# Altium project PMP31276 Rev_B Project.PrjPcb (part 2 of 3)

## Sheet PMP31276 Rev_B LLC Schematic.SchDoc: LLC Resonant converter
size 431 x 317 mm; Date: Not shown in title block; ApprovedBy: Not shown in title block; CheckedBy: Not shown in title block; Author: Not shown in title block; CompanyName: Not shown in title block; DrawnBy: R. Scibilia; Engineer: R. Scibilia; Organization: Not shown in title block; Address1: Not shown in title block; Address2: Not shown in title block; Address3: Not shown in title block; Address4: Not shown in title block; DocumentNumber: 1; Revision: Use project parameter SCH_Rev; SheetNumber: 2; SheetTotal: 5; PageSetup: Record=PageOptions¦CenterHorizontal=True¦CenterVertical=True¦PrintScale=1.00¦XCorrection=1.00¦YCorrection=1.00¦PrintKind=0¦BorderSize=5000000¦LeftOffset=0¦BottomOffset=0¦Orientation=2¦PaperLength=1000¦PaperWidth=1000¦Scale=100¦PaperSource=15¦PrintQuality=600¦MediaType=1¦DitherType=10¦PaperKind=Letter¦PrintScaleMode=1
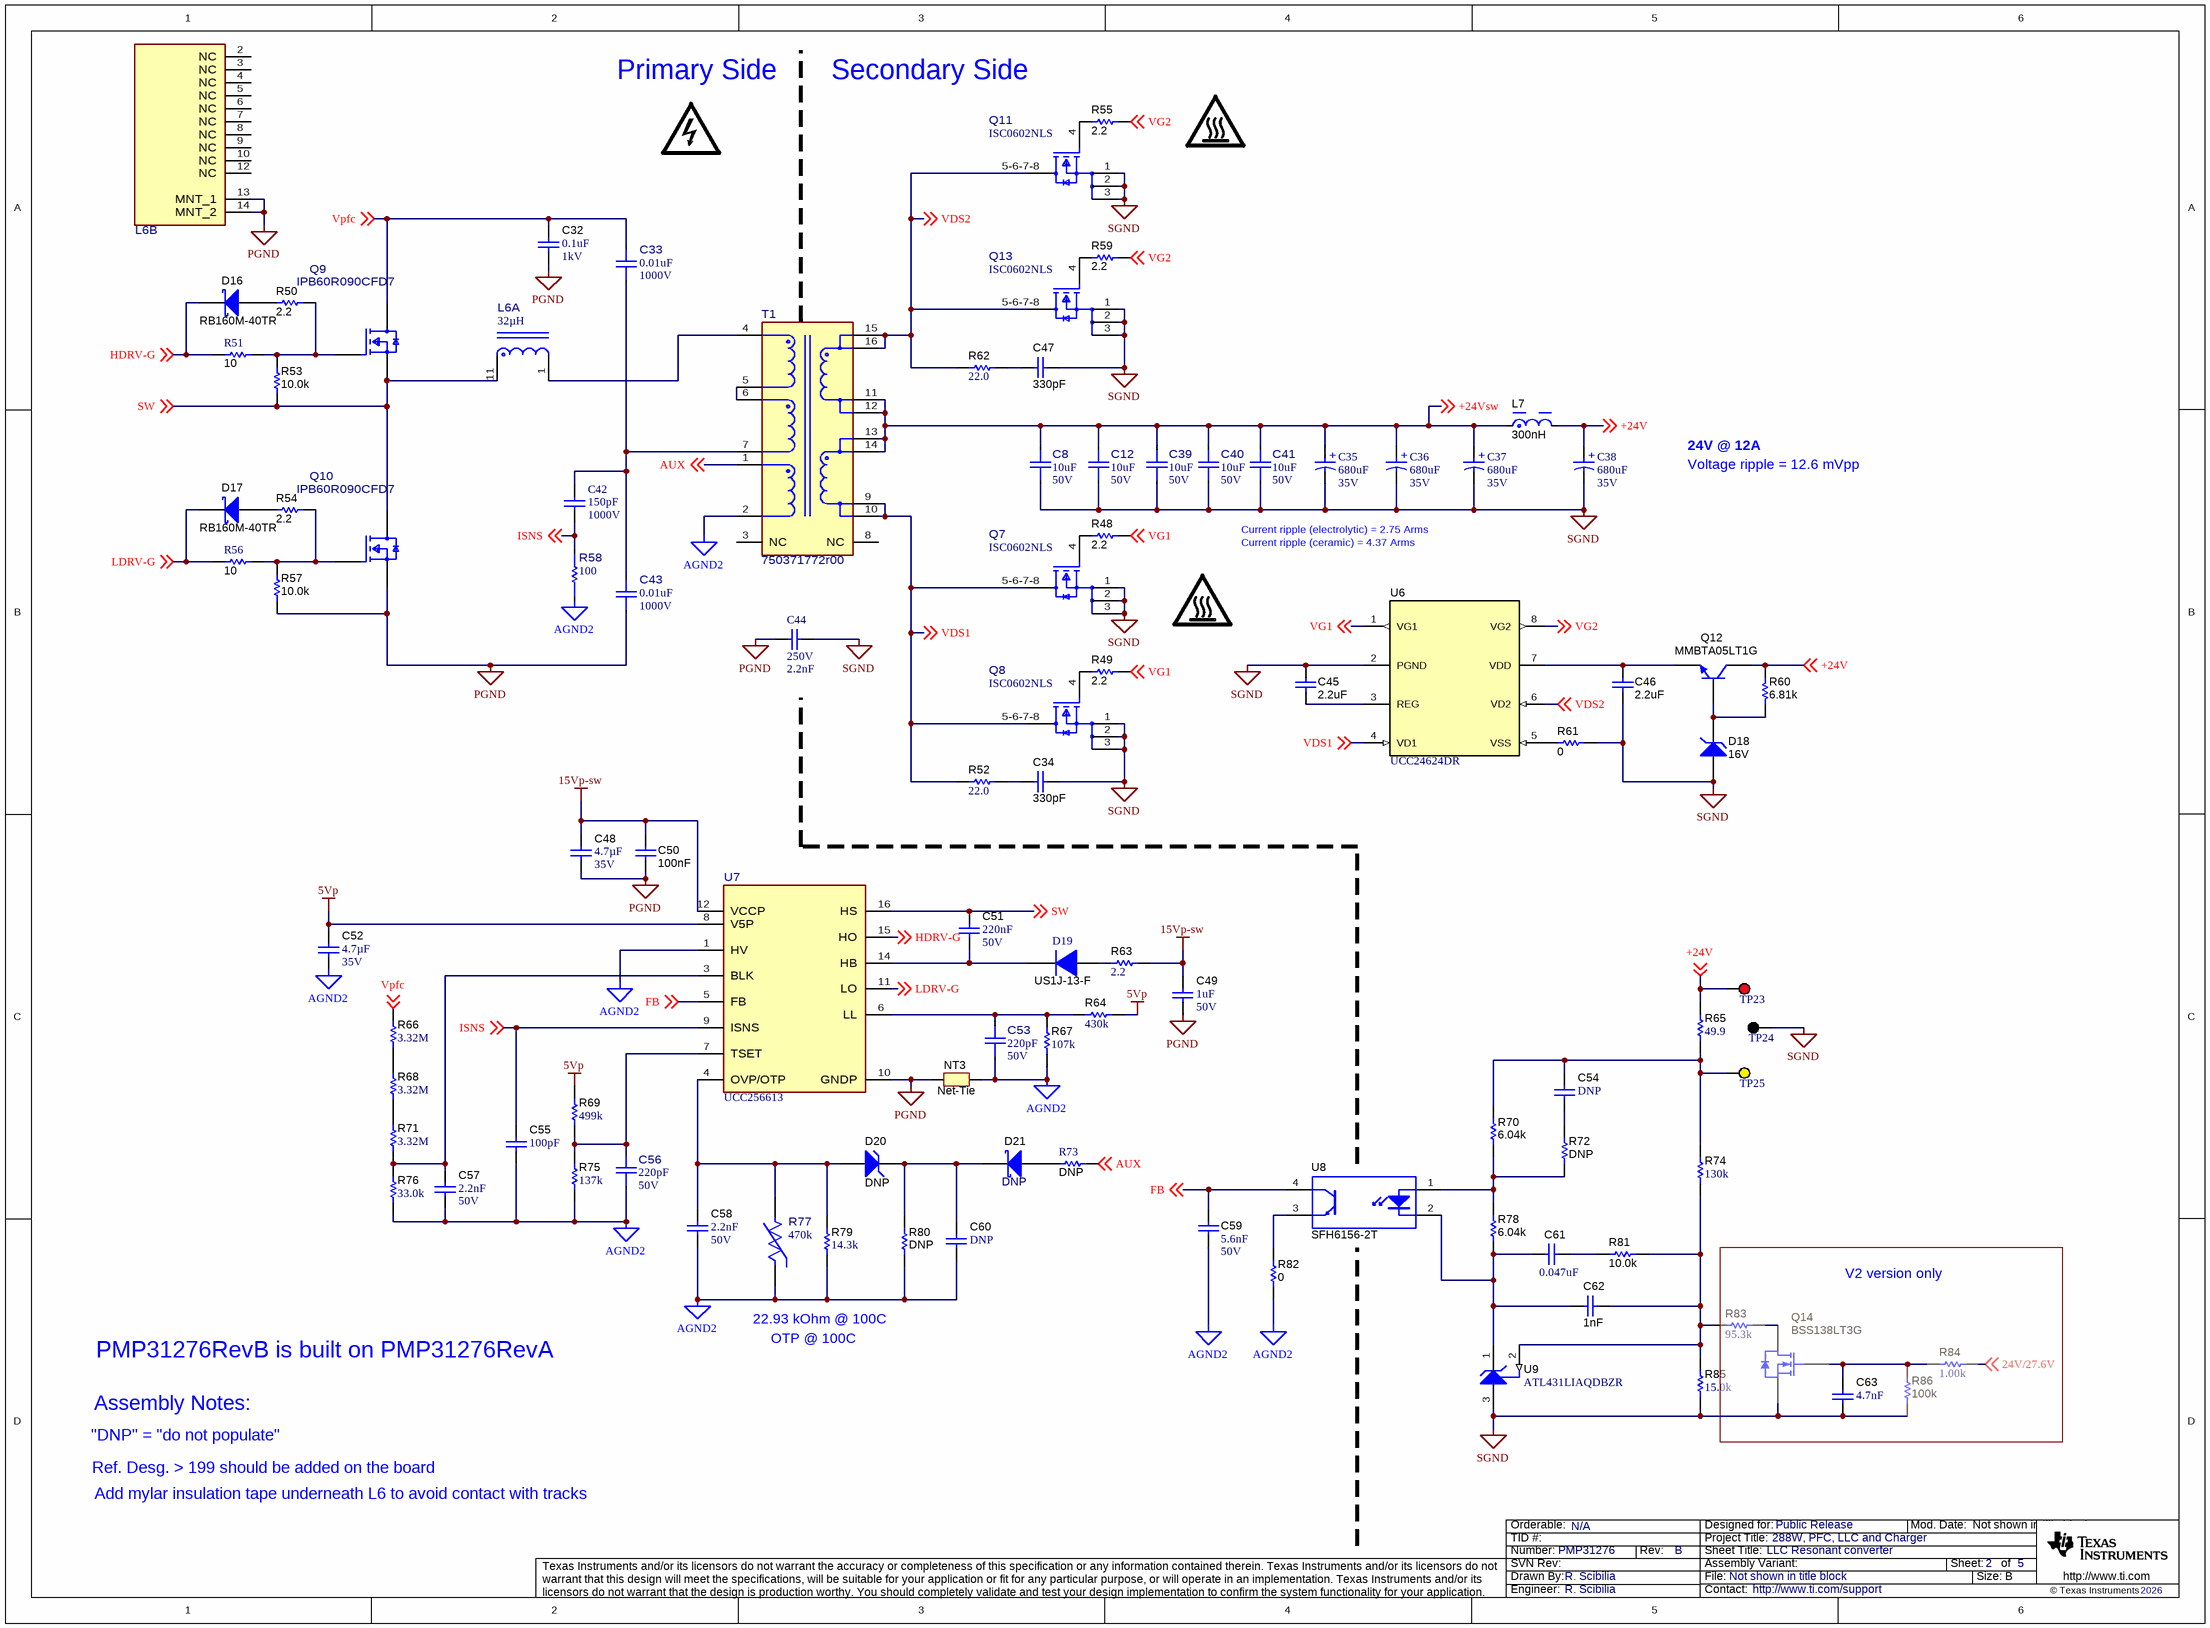
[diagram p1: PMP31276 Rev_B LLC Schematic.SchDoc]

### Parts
(Parts that share a designator on the sheet are numbered #1, #2 ... from top to bottom, then left to right.)
C8  ValueDisplayed: 10uF  VDC_V: 50V  [FP-885012209073_1210-MFG]  (hidden comment: 885012209073)
C12  ValueDisplayed: 10uF  VDC_V: 50V  [FP-885012209073_1210-MFG]  (hidden comment: 885012209073)
C32  VDC_V: 1kV  ValueDisplayed: 0.1uF  [1812_254]  (hidden comment: 885382211002)
C33  VDC_V: 1000V  ValueDisplayed: 0.01uF  [FP-CKC18C103KWGACAUTO_1812-MFG]  (hidden comment: CKC18C103JDGACAUTO)
C34  ValueDisplayed: 330pF  [1206]  (hidden comment: 885012008070)
C35  value 680uF  Rated Voltage (DC): 35V  [WCAP-ASLL_D12.5H14]  (hidden comment: 865060562010)
C36  value 680uF  Rated Voltage (DC): 35V  [WCAP-ASLL_D12.5H14]  (hidden comment: 865060562010)
C37  value 680uF  Rated Voltage (DC): 35V  [WCAP-ASLL_D12.5H14]  (hidden comment: 865060562010)
C38  value 680uF  Rated Voltage (DC): 35V  [WCAP-ASLL_D12.5H14]  (hidden comment: 865060562010)
C39  ValueDisplayed: 10uF  VDC_V: 50V  [FP-885012209073_1210-MFG]  (hidden comment: 885012209073)
C40  ValueDisplayed: 10uF  VDC_V: 50V  [FP-885012209073_1210-MFG]  (hidden comment: 885012209073)
C41  ValueDisplayed: 10uF  VDC_V: 50V  [FP-885012209073_1210-MFG]  (hidden comment: 885012209073)
C42  value 150pF  Rated Voltage (DC): 1000V  [WCAP-CSMH_1206_L3.2W1.6H1.25]  (hidden comment: 885342208016)
C43  VDC_V: 1000V  ValueDisplayed: 0.01uF  [FP-CKC18C103KWGACAUTO_1812-MFG]  (hidden comment: CKC18C103JDGACAUTO)
C44  value 2.2nF  Rated Voltage (AC): 250V  [WCAP-CSSA_2211_L5.7W2.8H2.5]  (hidden comment: 8853522130151)
C45  ValueDisplayed: 2.2uF  [0603]  (hidden comment: GRM188R6YA225KA12D)
C46  ValueDisplayed: 2.2uF  [0603]  (hidden comment: GRM188R6YA225KA12D)
C47  ValueDisplayed: 330pF  [1206]  (hidden comment: 885012008070)
C48  Cap_F: 4.7µF  VDC_V: 35V  [0805_HV]  (hidden comment: C2012X7R1V475K125AC)
C49  VDC_V: 50V  ValueDisplayed: 1uF  [0603]  (hidden comment: C1608X6S1H105K080AC)
C50  Cap_F: 100nF  [0603]  (hidden comment: 885012206095)
C51  Cap_F: 220nF  VDC_V: 50V  [0603]  (hidden comment: C1608X7R1H224K080AB)
C52  Cap_F: 4.7µF  VDC_V: 35V  [0805_HV]  (hidden comment: C2012X7R1V475K125AC)
C53  ValueDisplayed: 220pF  VDC_V: 50V  [FP-C0603C221J5GAC7867_0603-IPC_B]  (hidden comment: C0603C221J5GAC7867)
C54  DNP  [0603]
C55  ValueDisplayed: 100pF  [0603]  (hidden comment: 885012006057)
C56  ValueDisplayed: 220pF  VDC_V: 50V  [FP-C0603C221J5GAC7867_0603-IPC_B]  (hidden comment: C0603C221J5GAC7867)
C57  Cap_F: 2.2nF  VDC_V: 50V  [0603]  (hidden comment: C0603C222K5RAC)
C58  Cap_F: 2.2nF  VDC_V: 50V  [0603]  (hidden comment: C0603C222K5RAC)
C59  Cap_F: 5.6nF  VDC_V: 50V  [0603]  (hidden comment: C0603C222K5RACTU)
C60  DNP  [0603]
C61  ValueDisplayed: 0.047uF  [0603]  (hidden comment: C1608X5R1H473K080AA)
C62  Cap_F: 1nF  [0603]  (hidden comment: 885012206083)
C63  Cap_F: 4.7nF  [0603]  (hidden comment: 885012206087)
D16  RB160M-40TR  [SOD-123]
D17  RB160M-40TR  [SOD-123]
D18  value 16V  [SOD-323]  (hidden comment: MM3Z16VST1G)
D19  value US1J-13-F  [SMA]  (hidden comment: DIODE)
D20  DNP  [SOD-323]
D21  DNP  [SOD-123F]
L6  Ind_H: 32µH  [FP-750371775r00_PTH_22MM0_22MM0-MFG]  (hidden comment: 750371775r00)  (parts A,B of 2)
L7  value 300nH  [FP-7443081030_SMT_IND_9MM4_6MM2-MFG]  (hidden comment: 7443081030)
LOGO?#4  CAUTION HOT SURFACE  [IEC_HotSurface_Small]  (value not drawn)  (graphical)
LOGO?#5  DANGER HIGH VOLTAGE  [IEC_HighVoltage_Small]  (value not drawn)  (graphical)
LOGO?#6  CAUTION HOT SURFACE  [IEC_HotSurface_Small]  (value not drawn)  (graphical)
NT3  Net-Tie  [Net-Tie_20milWide_60milLong]  (net tie, no BOM)
Q7  ISC0602NLS  [FP-ISC0603NLSATMA1_TDSON-8-MFG]
Q8  ISC0602NLS  [FP-ISC0603NLSATMA1_TDSON-8-MFG]
Q9  IPB60R090CFD7  [FP-IPB60R105CFD7ATMA1_D2PAK-MFG]
Q10  IPB60R090CFD7  [FP-IPB60R105CFD7ATMA1_D2PAK-MFG]
Q11  ISC0602NLS  [FP-ISC0603NLSATMA1_TDSON-8-MFG]
Q12  MMBTA05LT1G  [SOT-23]
Q13  ISC0602NLS  [FP-ISC0603NLSATMA1_TDSON-8-MFG]
Q14  BSS138LT3G  [SOT-23]
R48  ValueDisplayed: 2.2  [0805_HV]  (hidden comment: RC0805JR-072R2L)
R49  ValueDisplayed: 2.2  [0805_HV]  (hidden comment: RC0805JR-072R2L)
R50  ValueDisplayed: 2.2  [0805_HV]  (hidden comment: RC0805JR-072R2L)
R51  ValueDisplayed: 10  [0805_HV1]  (hidden comment: Resistor)
R52  ValueDisplayed: 22.0  [1206]  (hidden comment: RC1206FR-0722RL)
R53  ValueDisplayed: 10.0k  [0603]  (hidden comment: Resistor)
R54  ValueDisplayed: 2.2  [0805_HV]  (hidden comment: RC0805JR-072R2L)
R55  ValueDisplayed: 2.2  [0805_HV]  (hidden comment: RC0805JR-072R2L)
R56  ValueDisplayed: 10  [0805_HV1]  (hidden comment: Resistor)
R57  ValueDisplayed: 10.0k  [0603]  (hidden comment: Resistor)
R58  value 100  [FP-WCR0805LF1000FPLT_0805-MFG]  (hidden comment: WCR0805LF1000FPLT)
R59  ValueDisplayed: 2.2  [0805_HV]  (hidden comment: RC0805JR-072R2L)
R60  ValueDisplayed: 6.81k  [0603]  (hidden comment: RC0603FR-076K81L)
R61  ValueDisplayed: 0  [0603]  (hidden comment: RMCF0603ZT0R00)
R62  ValueDisplayed: 22.0  [1206]  (hidden comment: RC1206FR-0722RL)
R63  ValueDisplayed: 2.2  [0805_HV]  (hidden comment: RC0805JR-072R2L)
R64  ValueDisplayed: 430k  [0603]  (hidden comment: RC0603FR-07430KL)
R65  ValueDisplayed: 49.9  [0603]  (hidden comment: RC0603FR-0749R9L)
R66  ValueDisplayed: 3.32M  [1206]  (hidden comment: CRCW12063M32FKEA)
R67  ValueDisplayed: 107k  [0603]  (hidden comment: RC0603FR-07107KL)
R68  ValueDisplayed: 3.32M  [1206]  (hidden comment: CRCW12063M32FKEA)
R69  ValueDisplayed: 499k  [0603]  (hidden comment: RC0603FR-07499KL)
R70  ValueDisplayed: 6.04k  [0603]  (hidden comment: Resistor)
R71  ValueDisplayed: 3.32M  [1206]  (hidden comment: CRCW12063M32FKEA)
R72  DNP  [0603]
R73  DNP  [0805_HV1]
R74  ValueDisplayed: 130k  [0603]  (hidden comment: RC0603FR-07130KL)
R75  ValueDisplayed: 137k  [0603]  (hidden comment: RC0603FR-07137KL)
R76  ValueDisplayed: 33.0k  [0603]  (hidden comment: RC0603FR-0733KL)
R77  value 470k  [FP-B57371V2474J060_0603-MFG]  (hidden comment: B57371V2474J060)
R78  ValueDisplayed: 6.04k  [0603]  (hidden comment: Resistor)
R79  ValueDisplayed: 14.3k  [0603]  (hidden comment: RC0603FR-0714K3L)
R80  DNP  [0603]
R81  ValueDisplayed: 10.0k  [0603]  (hidden comment: Resistor)
R82  ValueDisplayed: 0  [0603]  (hidden comment: RMCF0603ZT0R00)
R83  ValueDisplayed: 95.3k  [0603]  (hidden comment: RC0603FR-0795K3L)
R84  ValueDisplayed: 1.00k  [0603]  (hidden comment: RC0603FR-071KL)
R85  ValueDisplayed: 15.0k  [0603]  (hidden comment: RC0603FR-0715KL)
R86  ValueDisplayed: 100k  [0603]  (hidden comment: CRCW0603100KFKEA)
T1  750371772r00  [FP-750371772r00_PTH16_41MM9_44MM0-MFG]
TP23  5000  [Keystone5000]  (value not drawn)
TP24  5001  [Keystone5001]  (value not drawn)
TP25  5004  [Keystone5004]  (value not drawn)
U6  UCC24624DR  [D0008A_N]
U7  UCC256613  [DDB0014A-MFG]
U8  SFH6156-2T  [SMD-4]
U9  ATL431LIAQDBZR  [DBZ0003A_N]

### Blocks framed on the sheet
V2 version only: C63 Q14 R83 R84 R86

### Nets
5Vp: C52.1 R64.2 R69.2 U7.8(V5P)
15Vp-sw: C48.1 C49.1 C50.1 R63.2 U7.12(VCCP)
AGND2: C52.2 C53.1 C55.2 C56.1 C57.2 C58.2 C59.2 C60.2 NT3.2 R58.1 R67.1 R75.1 R76.1 R77.1 R79.1 R80.2 R82.1 T1.2 U7.1(HV)
PGND: C32.2 C43.1 C44.1 C48.2 C49.2 C50.2 L6.13(MNT_1) L6.14(MNT_2) NT3.1 Q10.3(Source) R57.1 U7.10(GNDP)
SGND: C8.1 C12.1 C34.1 C35.2(N) C36.2(N) C37.2(N) C38.2(N) C39.1 C40.1 C41.1 C44.2 C45.1 C46.2 C47.1 C63.2 D18.2(A) Q7.1(Source) Q7.2(Source) Q7.3(Source) Q8.1(Source) Q8.2(Source) Q8.3(Source) Q11.1(Source) Q11.2(Source) Q11.3(Source) Q13.1(Source) Q13.2(Source) Q13.3(Source) Q14.2(S) R61.1 R85.1 R86.2 TP24.1 U6.2(PGND) U9.3(ANODE)
24V/27.6V: R84.1 ; off-sheet 24V/27.6V
+24V: C38.1(P) L7.2 Q12.3(C) R60.2 R65.2 TP23.1 ; off-sheet +24V
+24Vsw: C8.2 C12.2 C35.1(P) C36.1(P) C37.1(P) C39.2 C40.2 C41.2 L7.1 T1.11 T1.12 T1.13 T1.14 ; off-sheet +24Vsw
AUX: R73.2 T1.1 ; off-sheet AUX
FB: C59.1 U7.5(FB) U8.4(C) ; off-sheet FB
HDRV-G: D16.1(K) R51.1 U7.15(HO) ; off-sheet HDRV-G
ISNS: C42.1 C55.1 R58.2 U7.9(ISNS) ; off-sheet ISNS
LDRV-G: D17.1(K) R56.1 U7.11(LO) ; off-sheet LDRV-G
SW: C51.1 L6.11 Q9.3(Source) Q10.4(Drain) R53.1 U7.16(HS) ; off-sheet SW
VDS1: Q7.5-6-7-8(Drain) Q8.5-6-7-8(Drain) R52.1 T1.9 T1.10 U6.4(VD1) ; off-sheet VDS1
VDS2: Q11.5-6-7-8(Drain) Q13.5-6-7-8(Drain) R62.1 T1.15 T1.16 U6.6(VD2) ; off-sheet VDS2
VG1: R48.1 R49.1 U6.1(VG1) ; off-sheet VG1
VG2: R55.1 R59.1 U6.8(VG2) ; off-sheet VG2
Vpfc: C32.1 C33.2 Q9.4(Drain) R66.2 ; off-sheet Vpfc
NetC33_1: C33.1 C42.2 C43.2 T1.7
NetC34_2: C34.2 R52.2
NetC45_2: C45.2 U6.3(REG)
NetC46_1: C46.1 Q12.2(E) U6.7(VDD)
NetC47_2: C47.2 R62.2
NetC51_2: C51.2 D19.1(K) U7.14(HB)
NetC53_2: C53.2 R64.1 R67.2 U7.6(LL)
NetC54_1: C54.1 R65.1 R70.2 R74.2 TP25.1
NetC54_2: C54.2 R72.1
NetC56_2: C56.2 R69.1 R75.2 U7.7(TSET)
NetC57_1: C57.1 R71.1 R76.2 U7.3(BLK)
NetC58_1: C58.1 D20.2(A) R77.2 R79.2 U7.4(OVP/OTP)
NetC60_1: C60.1 D20.1(K) D21.1(K) R80.1
NetC61_1: C61.1 R81.1
NetC61_2: C61.2 C62.1 R78.1 U8.2(K) U9.1(CATHODE)
NetC62_2: C62.2 R74.1 R81.2 R83.1 R85.2 U9.2(REF)
NetC63_1: C63.1 Q14.1(G) R84.2 R86.1
NetD16_2: D16.2(A) R50.1
NetD17_2: D17.2(A) R54.1
NetD18_1: D18.1(K) Q12.1(B) R60.1
NetD19_2: D19.2(A) R63.1
NetD21_2: D21.2(A) R73.1
NetL6_1: L6.1 T1.4
NetQ7_4: Q7.4(Gate) R48.2
NetQ8_4: Q8.4(Gate) R49.2
NetQ9_1: Q9.1(Gate) R50.2 R51.2 R53.2
NetQ10_1: Q10.1(Gate) R54.2 R56.2 R57.2
NetQ11_4: Q11.4(Gate) R55.2
NetQ13_4: Q13.4(Gate) R59.2
NetQ14_3: Q14.3(D) R83.2
NetR61_2: R61.2 U6.5(VSS)
NetR66_1: R66.1 R68.2
NetR68_1: R68.1 R71.2
NetR70_1: R70.1 R72.2 R78.2 U8.1(A)
NetR82_2: R82.2 U8.3(E)
NetT1_5: T1.5 T1.6

Not connected (* = marked no-connect by the designer): L6 2(NC) 3(NC) 4(NC) 5(NC) 6(NC) 7(NC) 8(NC) 9(NC) 10(NC) 12(NC); T1 3(NC) 8(NC)

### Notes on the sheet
- (near LOGO?#5) Primary Side
- Secondary Side
- 24V @ 12A
- Voltage ripple = 12.6 mVpp
- Current ripple (electrolytic) = 2.75 Arms
- Current ripple (ceramic) = 4.37 Arms
- 22.93 kOhm @ 100C
- PMP31276RevB is built on PMP31276RevA
- OTP @ 100C
- Assembly Notes:
- "DNP" = "do not populate"
- Ref. Desg. > 199 should be added on the board
- Add mylar insulation tape underneath L6 to avoid contact with tracks

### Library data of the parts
C8 C12 C39-C41 = CMP-0097489-1: 10 µF ±10% 50V Ceramic Capacitor X7R 1210 (3225 Metric); Manufacturer: Wurth Electronics; SizeZ_mm: 2.8mm; AEC Qualified: No; Value: 10µF; TempCo: 15%
C32 = CMP-0009326-2: CAP, CERM, 0.1 uF, 1000 V, +/- 10%, X7R, 1812; Manufacturer: Wuerth; TaMin_C: -55°C; Polarized: N; SizeAreaWB_mm2: 23.1; Value1: Unknown; U/M: EA; Value: 0.1uF; TaMax_C: 125°C; SizeZ_mm: 2.54; SizeX_mm: 4.5; SizeY_mm: 3.2; Cap_Case: 1812; Value2: 1000V; SizeArea_mm2: 14.4; Cap_F: 100nF; AEC Category: Q200
C33 C43 = CMP-0097104-1: 10000 pF ±5% 1000V Ceramic Capacitor C0G, NP0 1812 (4532 Metric); Manufacturer: KEMET; TempCo: 30ppm/°C; Value: 10nF; AEC Grade: Grade 0; SizeZ_mm: 2.2mm; AEC Qualified: Yes; Tolerance_%: 10%
C34 C47 = CMP-0008475-2: CAP, CERM, 330 pF, 100 V, +/- 5%, C0G/NP0, 1206; Manufacturer: Wuerth; TaMin_C: -55°C; ESR_ohm: 3.92d; Polarized: N; SizeAreaWB_mm2: 10.92; Value1: 0.392 ohm; U/M: EA; Value: 330pF; TaMax_C: 125°C; SizeZ_mm: 1.35; SizeX_mm: 3.2; SizeY_mm: 1.6; Value2: 100V; SizeArea_mm2: 5.12; CompType: Capacitor; AEC Category: Q200
C35-C38 = CMP-0110502-1: WCAP-ASLL Aluminum Electrolytic Capacitor, V-Chip, D12.5 x H14mm, 680µF, 35V; Manufacturer: Wurth Elektronik; Capacitance Tolerance: +/-20%; Dissipation Factor: 14%; Endurance: 5000h; Leakage Current: 238uA; Ripple Current: 1150mA; Technical Reference: ASEH140681M035DVCTGE000
C42 = CMP-0108719-1: WCAP-CSMH Multilayer Ceramic Chip Capacitor, Mid and High Voltage, size 1206, X7R Class II, 150pF, 1000VDC; Manufacturer: Wurth Elektronik; Capacitance Tolerance: 10%; Case/Size Code: 1206; Dissipation Factor: 2.5%; Insulation Resistance: 10GOhm; Technical Reference: X7R1206151KA00DFCT10000
C44 = CMP-0112567-1: WCAP-CSSA Multilayer Ceramic Chip Safety Capacitor, size 2211, X7R Class II, 2.2nF, 250VAC; Manufacturer: Wurth Elektronik; Capacitance Tolerance: +/-10%; Case/Size Code: 2211; Dissipation Factor: 2.5%; Impulse Voltage: 5000VDC; Insulation Resistance: 10GOhm; Safety Class: X1/Y2; Technical Reference: X7R2211222KE00IFCT1B000
C45 C46 = CMP-0007356-5: CAP, CERM, 2.2 uF, 35 V, +/- 10%, X5R, 0603; Manufacturer: MuRata; TaMin_C: -55°C; Polarized: N; SizeAreaWB_mm2: 4.68; Value1: Unknown; U/M: EA; Value: 2.2uF; TaMax_C: 85°C; SizeZ_mm: 1; SizeX_mm: 1.6; SizeY_mm: 0.8; Value2: 35V; SizeArea_mm2: 1.28; CompType: Capacitor; Cap_F: 2.2µF; AEC Category: Q200
C48 C52 = CMP-0007885-2: CAP, CERM, 4.7 uF, 35 V, +/- 10%, X7R, 0805; Manufacturer: TDK; TaMin_C: -55°C; ESR_ohm: 2.346m; Polarized: N; SizeAreaWB_mm2: 6.75; Value1: 0.002346 ohm; U/M: EA; Value: 4.7uF; TaMax_C: 125°C; SizeZ_mm: 1.45; SizeX_mm: 2; SizeY_mm: 1.25; Cap_Case: 0805; SizeArea_mm2: 2.5; IRMS_A: 4.2602A; AEC Category: Q200
C49 = CMP-0007029-4: CAP, CERM, 1 uF, 50 V, +/- 10%, X6S, 0603; Manufacturer: TDK; TaMin_C: -55°C; ESR_ohm: 5.522m; Polarized: N; SizeAreaWB_mm2: 4.68; Value1: 0.005522 ohm; U/M: EA; Value: 1uF; TaMax_C: 105°C; SizeZ_mm: 1; SizeX_mm: 1.6; SizeY_mm: 0.8; SizeArea_mm2: 1.28; Cap_F: 1µF; IRMS_A: 2.2162A; AEC Category: Q200
C50 = CMP-0006837-3: CAP, CERM, 0.1 uF, 50 V, +/- 10%, X7R, 0603; Manufacturer: Wurth Elektronik; TaMin_C: -55°C; Polarized: N; SizeAreaWB_mm2: 4.68; Value1: Unknown; U/M: EA; Value: 0.1uF; TaMax_C: 125°C; SizeZ_mm: 1; SizeX_mm: 1.6; SizeY_mm: 0.8; Value2: 50V; SizeArea_mm2: 1.28; AEC Category: Q200
C51 = CMP-0007047-4: CAP, CERM, 0.22 uF, 50 V, +/- 10%, X7R, 0603; Manufacturer: TDK; TaMin_C: -55°C; ESR_ohm: 21.699m; Polarized: N; SizeAreaWB_mm2: 4.68; Value1: 0.021699 ohm; U/M: EA; Value: 0.22uF; TaMax_C: 125°C; SizeZ_mm: 1; SizeX_mm: 1.6; SizeY_mm: 0.8; SizeArea_mm2: 1.28; IRMS_A: 1.125A; AEC Category: Q200
C53 C56 = CMP-0045670-1: 220 pF ±5% 50V Ceramic Capacitor C0G, NP0 0603 (1608 Metric); Manufacturer: KEMET; AEC Qualified: No; SizeZ_mm: 0.87mm; TempCo: 30ppm/°C; Value: 220pF
C54 C60 = CMP-0007029-4: TaMin_C: -55°C; Polarized: N; TempCo: X6S; SizeAreaWB_mm2: 4.68; U/M: EA; TaMax_C: 105°C; Tolerance_%: 10%; SizeZ_mm: 1; SizeX_mm: 1.6; SizeY_mm: 0.8; SizeArea_mm2: 1.28; AEC Category: Q200
C55 = CMP-0006822-4: CAP, CERM, 100 pF, 50 V, +/- 5%, C0G/NP0, 0603; Manufacturer: Wurth Elektronik; TaMin_C: -55°C; Polarized: N; SizeAreaWB_mm2: 4.68; Value1: Unknown; U/M: EA; Value: 100pF; TaMax_C: 125°C; SizeZ_mm: 1; SizeX_mm: 1.6; SizeY_mm: 0.8; Value2: 50V; SizeArea_mm2: 1.28; AEC Category: Q200
C57 C58 = CMP-0006897-4: CAP, CERM, 2200 pF, 50 V, +/- 10%, X7R, 0603; Manufacturer: Kemet; TaMin_C: -55°C; Polarized: N; SizeAreaWB_mm2: 4.68; Value1: Unknown; U/M: EA; Value: 2200pF; TaMax_C: 125°C; SizeZ_mm: 1; SizeX_mm: 1.6; SizeY_mm: 0.8; SizeArea_mm2: 1.28; AEC Category: Q200
C59 = CMP-0006898-4: CAP, CERM, 5600 pF, 50 V, +/- 10%, X7R, 0603; Manufacturer: Kemet; PartNumber: C0603C562K5RACTU; TaMin_C: -55°C; Polarized: N; SizeAreaWB_mm2: 4.68; Value1: Unknown; U/M: EA; Value: 5600pF; TaMax_C: 125°C; SizeZ_mm: 1; SizeX_mm: 1.6; SizeY_mm: 0.8; SizeArea_mm2: 1.28; AEC Category: Q200
C61 = CMP-0007015-5: CAP, CERM, 0.047 uF, 50 V, +/- 10%, X5R, 0603; Manufacturer: TDK; TaMin_C: -55°C; ESR_ohm: 49.007m; Polarized: N; SizeAreaWB_mm2: 4.68; Value1: 0.049007 ohm; U/M: EA; TaMax_C: 85°C; SizeZ_mm: 1; SizeX_mm: 1.6; SizeY_mm: 0.8; Value2: 50V; SizeArea_mm2: 1.28; Cap_F: 47nF; IRMS_A: 767.528mA; AEC Category: Q200
C62 = CMP-0064933-4: CAP, CERM, 1000 pF, 50 V,+/- 10%, X7R, 0603; Manufacturer: Wurth Elektronik; TaMin_C: -55°C; Polarized: N; SizeAreaWB_mm2: 4.68; Value1: Unknown; U/M: EA; Value: 1000pF; TaMax_C: 125°C; SizeZ_mm: 1; SizeX_mm: 1.6; SizeY_mm: 0.8; Value2: 50V; SizeArea_mm2: 1.28; AEC Category: Q200
C63 = CMP-0006835-4: CAP, CERM, 4700 pF, 50 V, +/- 10%, X7R, 0603; Manufacturer: Wurth Elektronik; TaMin_C: -55°C; Polarized: N; SizeAreaWB_mm2: 4.68; Value1: Unknown; U/M: EA; Value: 4700pF; TaMax_C: 125°C; SizeZ_mm: 1; SizeX_mm: 1.6; SizeY_mm: 0.8; Value2: 50V; SizeArea_mm2: 1.28; AEC Category: Q200
D16 D17 = CMP-0028624-2: Diode, Schottky, 40 V, 1 A, SOD-123; PartNumber: RB160MM-40TR; Manufacturer: Rohm; Io_A: 1A; SizeAreaWB_mm2: 13.095; TJmax_C: 150°C; Green_REACh: Passed; SizeY_mm: 1.7; AEC Category: Q101; SizeArea_mm2: 6.545; SizeX_mm: 3.85; Value2: 0.55V; Value: 40V; Vf_V: 550mV; SizeZ_mm: 1.35
D18 = CMP-0085764-1: Diode, Zener, 16 V, 300 mW, SOD-323; Manufacturer: ON Semiconductor; Power_W: 300mW; SizeZ_mm: 1; SizeArea_mm2: 3.645; SizeX_mm: 2.7; SizeY_mm: 1.35; RJA_CperW: 416; Value1: 0.3W; SizeAreaWB_mm2: 8.695; AEC Qualified: N; AEC Category: Q101
D19 = CMP-0077027-2: Diode, Ultrafast, 600 V, 1 A, SMA; Manufacturer: Diodes Inc.; Vf_V: 1.7V; Io_A: 1A; Vr_V: 600V; TJmax_C: 150°C; AEC Category: Q101; Green_Lifecycle: Active; Green_REACh: Passed; SizeArea_mm2: 16.3228; SizeAreaWB_mm2: 37.3428; SizeX_mm: 5.59; SizeY_mm: 2.92; SizeZ_mm: 2.87
D20 = CMP-0085765-1: SizeX_mm: 2.7; RJA_CperW: 416; SizeArea_mm2: 3.645; AEC Category: Q101; SizeZ_mm: 1; Power_W: 300mW; AEC Qualified: Y; SizeY_mm: 1.35; SizeAreaWB_mm2: 8.695
D21 = CMP-0028377-2: TJmax_C: 150°C; Type: Schottky; Green_REACh: Incomplete; CompType: Diode; SizeY_mm: 1.6; SizeArea_mm2: 5.6; AEC Category: Q101; SizeZ_mm: 1.1; SizeX_mm: 3.5; Green_Lifecycle: Not Set; SizeAreaWB_mm2: 11.7
L6 = CMP-0120633-1: INDUCTOR; Manufacturer: Wurth; AEC Qualified: No; DCR_ohm: 12.1m; Isat: 6A; SizeZ_mm: 17.27mm; Value: 32uH; Test Frequency: 10kHz; Tolerance_%: 10%
L7 = CMP-0093738-1: WE-HCM SMT High Current Flat Wire Inductor 34.6A 300nH @ 10% 100kHz 0.3045mohm; Manufacturer: Wurth Electronics; AEC Qualified: No; Self Resonant Frequency: 33MHz; SizeZ_mm: 8.1mm; TaMin_C: -40°C; Isat: 22.2A; Shrouded: true; TaMax_C: +85°C; DCR_ohm: 304.5µ
LOGO?#4 LOGO?#6 = IEC_HotSurface: IEC 61010-1 Hot Surface Warning; SymbolCreator: a0412235
LOGO?#5 = IEC_HighVoltage: IEC 61010-1 High Voltage Warning; SymbolCreator: a0412235
NT3 = CMP-0078142-6: Single point connection between nets.
Q7 Q8 Q11 Q13 = CMP-0096664-1: N-Channel 80 V 66A , Surrface Mount PG-TDSON-8-6; Manufacturer: Infineon; Turn Off Delay Time: 12ns; SizeZ_mm: 1mm; Typ Forward Diode Voltage: 0.88V; VdsMax_V: 1V; Drain To Source Breakdown Voltage: 80V; Power_W: 2.5W; Number Of Channels: 1; AEC Qualified: No; Turn On Delay Time: 4.8ns; Threshold Vgs Min: 1.1V; Reverse Recovery Time: 31ns; QgTyp_nC: 18nC @ 10V; ChMode: False; Threshold Vgs Max: 2.3V; Vgs_V: 20V; TJmax_C: +150°C; Transconductance: 43S; Reverse Recovery Charge: 26nC; Rthja Max: 50°C/W; Pulse Drain Current: 224A; Rdson45_ohm: 8.5m
Q9 Q10 = CMP-0065576-1: Power Transistor MOSFET N-Channel Enhancement 600V 21A 3-Pin D2PAK T/R; Manufacturer: Infineon; AEC Qualified: No; IdsMax_A: 25A; QgTyp_nC: 51nC @ 10V; Rdson45_ohm: 75m; SizeZ_mm: 4.5mm; Vgs_V: 20V; ChMode: False; Input Capacitace At Vds: 2103pF @ 400V; Number Of Channels: 1; Power_W: 106W; Pulse Drain Current: 97A; Reverse Recovery Charge: 540nC; Reverse Recovery Time: 109ns; Rthja Max: 62°C/W; Standoff Height: 0.1mm; Threshold Vgs Max: 4.5V; Threshold Vgs Min: 3.5V; TJmax_C: +150°C; Turn Off Delay Time: 88ns; Turn On Delay Time: 33ns; Typ Forward Diode Voltage: 1V
Q12 = CMP-0000488-2: Transistor, NPN, 60 V, 0.5 A, AEC-Q101, SOT-23; Manufacturer: ON Semiconductor; TaMax_C: 150°C; Value1: 0.5 A; Vcesat1_V: 2.5dV; SizeX_mm: 2.5; SizeY_mm: 3; TaMin_C: -55°C; IcRated_A: 5dA; CompType: BJT; SizeZ_mm: 1.1; AEC Qualified: Y; SizeArea_mm2: 7.5; NPN: 1; Vceo_V: 60V; PNP: 0; AEC Category: Q101; SizeAreaWB_mm2: 14; U/M: EA
Q14 = CMP-0074582-1: MOSFET, N-CH, 50 V, .2 A, AEC-Q101, SOT-23; Alternate Manufacturer: None; Manufacturer: ON Semiconductor; SizeAreaWB_mm2: 14.0; Vgs_V: 20V; Value1: ? ohm; VdsMax_V: 50V; U/M: EA; IdsMax_A: 200mA; SizeZ_mm: 1.1; SizeX_mm: 2.5; SizeY_mm: 3.0; Value2: ? nC; SizeArea_mm2: 7.5; ChType: N; AEC Qualified: Y; AEC Category: Q101
R48-R50 R54 R55 R59 R63 = CMP-0020812-2: RES, 2.2, 5%, 0.125 W, 0805; Manufacturer: Yageo America; Power_W: 125mW; TempCo: 200 ppm/C; Value_Code: 2R20; U/M: EA; Value: 2.2; EIA_Code: E24; SizeX_mm: 2; SizeY_mm: 1.25; SizeZ_mm: 1.45; Value2: 0.125W; SizeArea_mm2: 2.5; VDC_V: 150V; AEC Category: Q200
R51 R56 = CMP-0020448-3: RES, 10, 5%, 0.125 W, AEC-Q200 Grade 0, 0805; PartNumber: CRCW080510R0JNEA; Manufacturer: Vishay-Dale; Value: 10; Value_Code: 10R0; Power_W: 125mW; Value2: 0.125W; VDC_V: 150V; TempCo: 200 ppm/C; EIA_Code: E24; AEC Category: Q200; AEC Grade: 0; AEC Qualified: Y; SizeArea_mm2: 2.5; SizeX_mm: 2; SizeY_mm: 1.25; SizeZ_mm: 1.45
R52 R62 = CMP-0018087-2: RES, 22.0, 1%, 0.25 W, 1206; Manufacturer: Yageo America; Power_W: 250mW; TempCo: 100 ppm/C; Value_Code: 22R0; U/M: EA; Value: 22.0; Res_ohm: 22; SizeX_mm: 3.2; SizeY_mm: 1.6; SizeZ_mm: 1.35; Value2: 0.25W; SizeArea_mm2: 5.12; VDC_V: 200V; AEC Category: Q200
R53 R57 R81 = CMP-0021998-4: RES, 10.0 k, 1%, 0.1 W, AEC-Q200 Grade 0, 0603; PartNumber: CRCW060310K0FKEA; Manufacturer: Vishay-Dale; Value: 10.0k; Res_ohm: 10k; Value_Code: 10k0; Power_W: 100mW; Value2: 0.1W; VDC_V: 75V; TempCo: 100 ppm/C; SizeArea_mm2: 1.28; SizeX_mm: 1.6; SizeY_mm: 0.8; SizeZ_mm: 1; EIA_Code: E96; AEC Category: Q200; AEC Qualified: Y; AEC Grade: 0
R58 = CMP-0095058-1: Thick Film Resistors - SMD 100 OHM 1% 0805 Package 125mW 150V 100ppm/C; Manufacturer: TT Electronics; TaMax_C: +155°C; AEC Qualified: Yes; SizeZ_mm: 0.65mm; TempCo: 200ppm/°C; AEC Grade: Grade 0; TaMin_C: -55°C
R60 = CMP-0023252-5: RES, 6.81 k, 1%, 0.1 W, 0603; Manufacturer: Yageo; Power_W: 100mW; TempCo: 100 ppm/C; Value_Code: 6k81; Value: 6.81k; EIA_Code: E96; SizeX_mm: 1.6; SizeY_mm: 0.8; SizeZ_mm: 1; Value2: 0.1W; SizeArea_mm2: 1.28; AEC Qualified: N; VDC_V: 75V; AEC Category: Q200; SizeAreaWB_mm2: 4.68
R61 R82 = CMP-0023343-3: RES, 0, 1%, 0.1 W, AEC-Q200 Grade 0, 0603; Manufacturer: Stackpole Electronics Inc; Power_W: 100mW; TempCo: ppm/C; U/M: EA; Value: 0; SizeX_mm: 1.6; SizeY_mm: 0.8; SizeZ_mm: 1; Value2: 0.1W; SizeArea_mm2: 1.28; AEC Qualified: Y; AEC Category: Q200
R64 = CMP-0023108-4: RES, 430 k, 1%, 0.1 W, 0603; Manufacturer: Yageo; Power_W: 100mW; TempCo: 100 ppm/C; Value: 430k; SizeX_mm: 1.6; SizeY_mm: 0.8; SizeZ_mm: 1; Value2: 0.1W; SizeArea_mm2: 1.28; AEC Qualified: N; VDC_V: 75V; AEC Category: Q200; SizeAreaWB_mm2: 4.68
R65 = CMP-0023143-5: RES, 49.9, 1%, 0.1 W, 0603; Manufacturer: Yageo; Power_W: 100mW; TempCo: 100 ppm/C; Value_Code: 49R9; Value: 49.9; EIA_Code: E96; SizeX_mm: 1.6; SizeY_mm: 0.8; SizeZ_mm: 1; Value2: 0.1W; SizeArea_mm2: 1.28; AEC Qualified: N; VDC_V: 75V; AEC Category: Q200; SizeAreaWB_mm2: 4.68
R66 R68 R71 = CMP-0016960-3: RES, 3.32 M, 1%, 0.25 W, AEC-Q200 Grade 0, 1206; Manufacturer: Vishay-Dale; Power_W: 250mW; TempCo: 100 ppm/C; Value_Code: 3M32; Value: 3.32Meg; EIA_Code: E96; SizeX_mm: 3.2; SizeY_mm: 1.6; SizeZ_mm: 1.35; Value2: 0.25W; SizeArea_mm2: 5.12; AEC Qualified: Y; VDC_V: 200V; AEC Category: Q200; AEC Grade: 0
R67 = CMP-0022741-4: RES, 107 k, 1%, 0.1 W, 0603; Manufacturer: Yageo; Power_W: 100mW; TempCo: 100 ppm/C; Value: 107k; EIA_Code: E96; SizeX_mm: 1.6; SizeY_mm: 0.8; SizeZ_mm: 1; Value2: 0.1W; SizeArea_mm2: 1.28; AEC Qualified: N; VDC_V: 75V; AEC Category: Q200; SizeAreaWB_mm2: 4.68
R69 = CMP-0023140-4: RES, 499 k, 1%, 0.1 W, 0603; Manufacturer: Yageo; Power_W: 100mW; TempCo: 100 ppm/C; Value: 499k; EIA_Code: E96; SizeX_mm: 1.6; SizeY_mm: 0.8; SizeZ_mm: 1; Value2: 0.1W; SizeArea_mm2: 1.28; AEC Qualified: N; VDC_V: 75V; AEC Category: Q200; SizeAreaWB_mm2: 4.68
R70 R78 = CMP-0022558-4: RES, 6.04 k, 1%, 0.1 W, AEC-Q200 Grade 0, 0603; PartNumber: CRCW06036K04FKEA; Manufacturer: Vishay-Dale; Value: 6.04k; Value_Code: 6k04; Power_W: 100mW; Value2: 0.1W; VDC_V: 75V; TempCo: 100 ppm/C; SizeArea_mm2: 1.28; SizeX_mm: 1.6; SizeY_mm: 0.8; SizeZ_mm: 1; EIA_Code: E96; AEC Category: Q200; AEC Qualified: Y; AEC Grade: 0
R72 R80 = CMP-0021990-4: Power_W: 100mW; TempCo: 100 ppm/C; Value1: 1%; EIA_Code: E96; SizeX_mm: 1.6; SizeY_mm: 0.8; SizeZ_mm: 1; Value2: 0.1W; SizeArea_mm2: 1.28; AEC Qualified: Y; VDC_V: 75V; AEC Category: Q200; AEC Grade: 0
R73 = CMP-0020448-3: Value: 10; Tolerance_%: 5%; Power_W: 125mW; TempCo: 200 ppm/C; EIA_Code: E24; AEC Category: Q200; AEC Grade: 0; AEC Qualified: Y; SizeArea_mm2: 2.5; SizeX_mm: 2; SizeY_mm: 1.25; SizeZ_mm: 1.45
R74 = CMP-0022784-4: RES, 130 k, 1%, 0.1 W, 0603; Manufacturer: Yageo; Power_W: 100mW; TempCo: 100 ppm/C; Value: 130k; EIA_Code: E96; SizeX_mm: 1.6; SizeY_mm: 0.8; SizeZ_mm: 1; Value2: 0.1W; SizeArea_mm2: 1.28; AEC Qualified: N; VDC_V: 75V; AEC Category: Q200; SizeAreaWB_mm2: 4.68
R75 = CMP-0022788-4: RES, 137 k, 1%, 0.1 W, 0603; Manufacturer: Yageo; Power_W: 100mW; TempCo: 100 ppm/C; Value: 137k; EIA_Code: E96; SizeX_mm: 1.6; SizeY_mm: 0.8; SizeZ_mm: 1; Value2: 0.1W; SizeArea_mm2: 1.28; AEC Qualified: N; VDC_V: 75V; AEC Category: Q200; SizeAreaWB_mm2: 4.68
R76 = CMP-0023037-5: RES, 33.0 k, 1%, 0.1 W, 0603; Manufacturer: Yageo; Power_W: 100mW; TempCo: 100 ppm/C; Value_Code: 33k0; Value: 33.0k; Res_ohm: 33k; SizeX_mm: 1.6; SizeY_mm: 0.8; SizeZ_mm: 1; Value2: 0.1W; SizeArea_mm2: 1.28; AEC Qualified: N; VDC_V: 75V; AEC Category: Q200; SizeAreaWB_mm2: 4.68
R77 = CMP-0096703-1: NTC Thermistor 470k 0603 (1608 Metric); Manufacturer: TDK; AEC Qualified: No; Res_ohm: 470kΩ; Power_W: 180mW; B 25 50: 4386K; B 25 100: 4480K; SizeZ_mm: 0.9mm; B 25 85: 4455K; B Tolerance: 3%; Tolerance_%: 5%
R79 = CMP-0022802-5: RES, 14.3 k, 1%, 0.1 W, 0603; Manufacturer: Yageo; Power_W: 100mW; TempCo: 100 ppm/C; Value_Code: 14k3; Value: 14.3k; EIA_Code: E96; SizeX_mm: 1.6; SizeY_mm: 0.8; SizeZ_mm: 1; Value2: 0.1W; SizeArea_mm2: 1.28; AEC Qualified: N; VDC_V: 75V; AEC Category: Q200; SizeAreaWB_mm2: 4.68
R83 = CMP-0023326-5: RES, 95.3 k, 1%, 0.1 W, 0603; Manufacturer: Yageo; Power_W: 100mW; TempCo: 100 ppm/C; Value_Code: 95k3; Value: 95.3k; EIA_Code: E96; SizeX_mm: 1.6; SizeY_mm: 0.8; SizeZ_mm: 1; Value2: 0.1W; SizeArea_mm2: 1.28; AEC Qualified: N; VDC_V: 75V; AEC Category: Q200; SizeAreaWB_mm2: 4.68
R84 = CMP-0022895-5: RES, 1.00 k, 1%, 0.1 W, 0603; Manufacturer: Yageo; Power_W: 100mW; TempCo: 100 ppm/C; Value_Code: 1k00; Value: 1.00k; EIA_Code: E96; Res_ohm: 1k; SizeX_mm: 1.6; SizeY_mm: 0.8; SizeZ_mm: 1; Value2: 0.1W; SizeArea_mm2: 1.28; AEC Qualified: N; VDC_V: 75V; AEC Category: Q200; SizeAreaWB_mm2: 4.68
R85 = CMP-0022816-5: RES, 15.0 k, 1%, 0.1 W, 0603; Manufacturer: Yageo; Power_W: 100mW; TempCo: 100 ppm/C; Value_Code: 15k0; Value: 15.0k; EIA_Code: E96; Res_ohm: 15k; SizeX_mm: 1.6; SizeY_mm: 0.8; SizeZ_mm: 1; Value2: 0.1W; SizeArea_mm2: 1.28; AEC Qualified: N; VDC_V: 75V; AEC Category: Q200; SizeAreaWB_mm2: 4.68
R86 = CMP-0021990-4: RES, 100 k, 1%, 0.1 W, AEC-Q200 Grade 0, 0603; Manufacturer: Vishay-Dale; Power_W: 100mW; TempCo: 100 ppm/C; Value: 100k; EIA_Code: E96; SizeX_mm: 1.6; SizeY_mm: 0.8; SizeZ_mm: 1; Value2: 0.1W; SizeArea_mm2: 1.28; AEC Qualified: Y; VDC_V: 75V; AEC Category: Q200; AEC Grade: 0
T1 = CMP-0120632-1: TRANSFORMER; Manufacturer: Wurth; DCR_ohm: 71m; Ind_H: 192µH; Ns1toNp: 8.33:1; Rsec1_ohm: 5m; SizeZ_mm: 31.75mm; AEC Qualified: No
TP23 = CMP-0055137-2: Test Point, Miniature, Red, TH; Manufacturer: Keystone Electronics; Green_REACh: Passed; Green_Lifecycle: Active; ContactFinish: Silver; CNHeader: FALSE; CT: TRUE
TP24 = CMP-0055138-2: Test Point, Miniature, Black, TH; Manufacturer: Keystone Electronics; ContactFinish: Silver; CNHeader: FALSE; Green_Lifecycle: Active; Green_REACh: Passed; CT: TRUE
TP25 = CMP-0055141-2: Test Point, Miniature, Yellow, TH; Manufacturer: Keystone Electronics; CT: TRUE; ContactFinish: Silver; Green_Lifecycle: Active; CNHeader: FALSE; Green_REACh: Passed
U6 = CMP-0079610-1: High Performance Synchronous Rectifier Driver for LLC Resonant Converter, D0008A (SOIC-8); Alternate Manufacturer: Texas Instruments; SizeAreaWB_mm2: 56.58; SizeZ_mm: 1.75; SizeX_mm: 4.9; SizeY_mm: 6.2; SizeArea_mm2: 30.38; CompType: IC; AEC Qualified: N; AEC Category: Q200
U7 = CMP-0125237-1: 750kHz Wide VIN/VOUT Range LLC Controller Optimized for Light-Load Efficiency; Manufacturer: Texas Instruments; SizeZ_mm: 1.75mm; AEC Qualified: No; AEC Grade: NA; Max Supply Voltage: 18.5V; Number Of Outputs: 2; Output Type: Other; Standoff Height: 0.1mm; Switching Frequency: 50-750kHz; TaMax_C: +125°C; TaMin_C: -40°C; TJmax_C: +150°C
U8 = CMP-0006172-3: Optocoupler, 5.3 kV, 63-125% CTR, SMT; Manufacturer: Vishay-Semiconductor; CTR (Max): 125%; CTR (Min): 63%; Voltage_Isolation_Vrms: 5.3kV
U9 = CMP-0084733-1: High Bandwidth Low-Iq Programmable Shunt Regulator, DBZ0003A (SOT-23-3); Alternate Manufacturer: Texas Instruments; CompType: IC; SizeX_mm: 2.5; AEC Qualified: N; SizeZ_mm: 1.12; AEC Category: Q200; SizeY_mm: 3; SizeAreaWB_mm2: 14; SizeArea_mm2: 7.5

## Sheet PMP31276 Rev_B Charger Schematic.SchDoc: Battery charger
size 431 x 279 mm; Date: Not shown in title block; ApprovedBy: Not shown in title block; CheckedBy: Not shown in title block; Author: Not shown in title block; CompanyName: Not shown in title block; DrawnBy: R. Scibilia; Engineer: Not shown in title block; Organization: Not shown in title block; Address1: Not shown in title block; Address2: Not shown in title block; Address3: Not shown in title block; Address4: Not shown in title block; DocumentNumber: 1; Revision: Use project parameter SCH_Rev; SheetNumber: 3; SheetTotal: 5; PageSetup: Record=PageOptions¦CenterHorizontal=True¦CenterVertical=True¦PrintScale=1.00¦XCorrection=1.00¦YCorrection=1.00¦PrintKind=0¦BorderSize=5000000¦LeftOffset=0¦BottomOffset=0¦Orientation=2¦PaperLength=1000¦PaperWidth=1000¦Scale=100¦PaperSource=15¦PrintQuality=600¦MediaType=1¦DitherType=10¦PaperKind=Letter¦PrintScaleMode=1
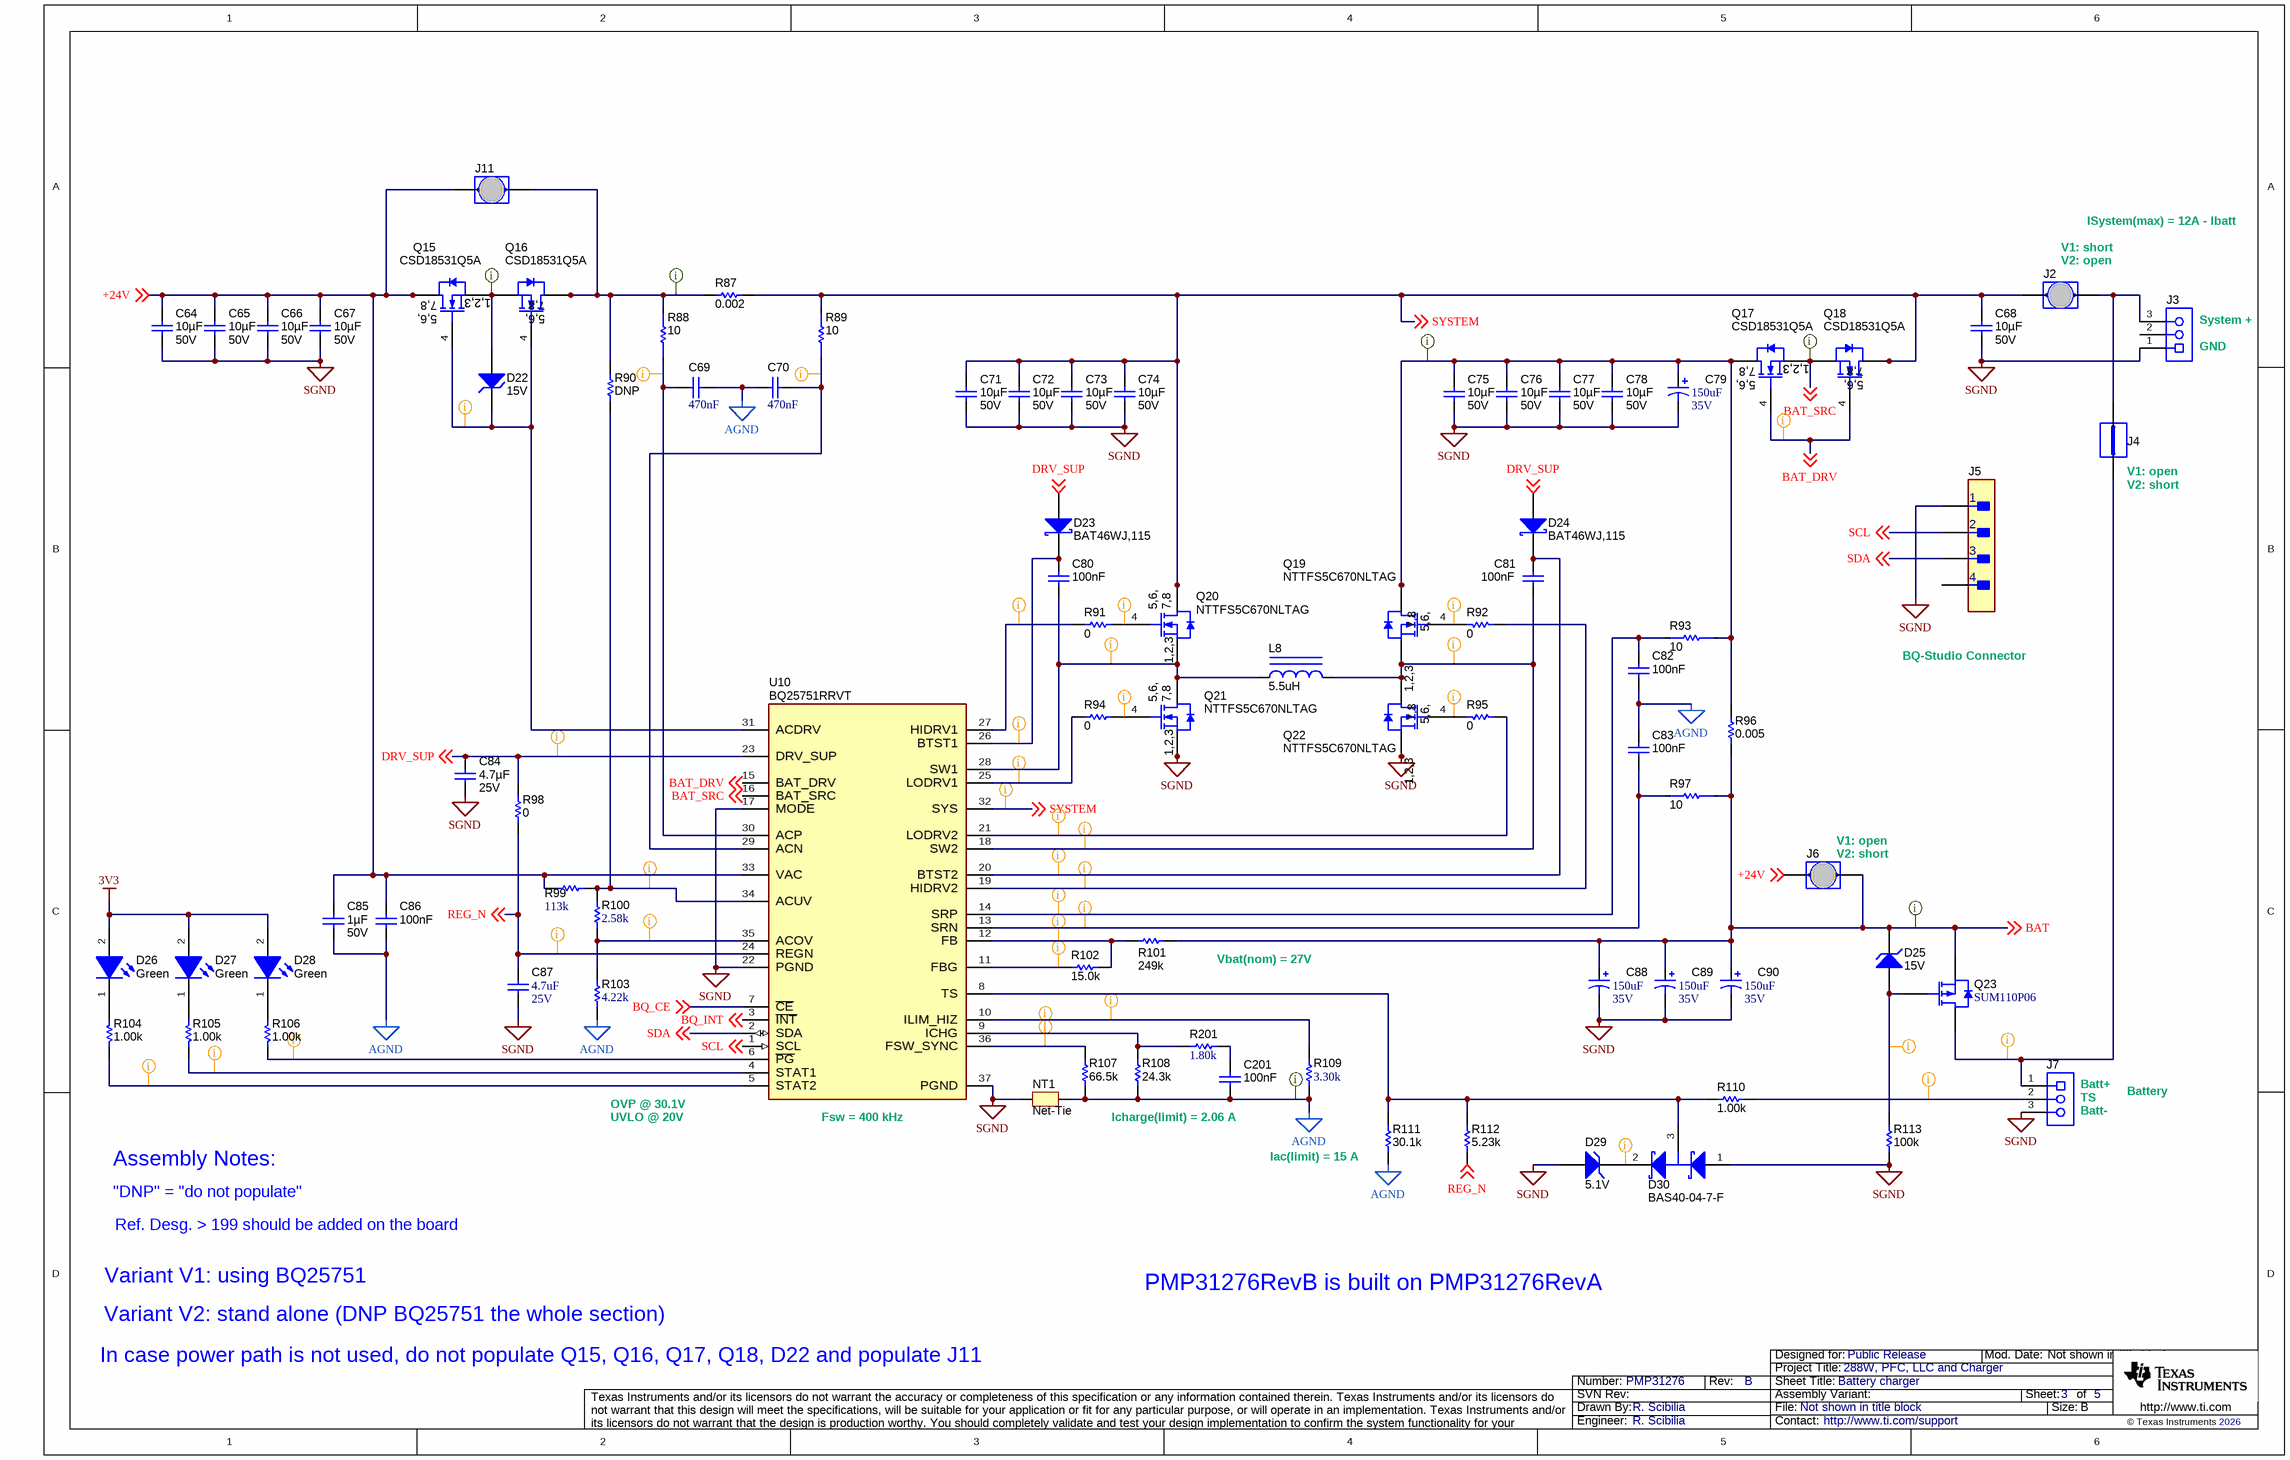
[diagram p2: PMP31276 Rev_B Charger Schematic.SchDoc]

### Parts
C64  VDC_V: 50V  ValueDisplayed: 10µF  [1210_280]  (hidden comment: 885012209073)
C65  VDC_V: 50V  ValueDisplayed: 10µF  [1210_280]  (hidden comment: 885012209073)
C66  VDC_V: 50V  ValueDisplayed: 10µF  [1210_280]  (hidden comment: 885012209073)
C67  VDC_V: 50V  ValueDisplayed: 10µF  [1210_280]  (hidden comment: 885012209073)
C68  VDC_V: 50V  ValueDisplayed: 10µF  [1210_280]  (hidden comment: 885012209073)
C69  Cap_F: 470nF  [0603]  (hidden comment: GRM188R71E474KA12D)
C70  Cap_F: 470nF  [0603]  (hidden comment: GRM188R71E474KA12D)
C71  VDC_V: 50V  ValueDisplayed: 10µF  [1210_280]  (hidden comment: 885012209073)
C72  VDC_V: 50V  ValueDisplayed: 10µF  [1210_280]  (hidden comment: 885012209073)
C73  VDC_V: 50V  ValueDisplayed: 10µF  [1210_280]  (hidden comment: 885012209073)
C74  VDC_V: 50V  ValueDisplayed: 10µF  [1210_280]  (hidden comment: 885012209073)
C75  VDC_V: 50V  ValueDisplayed: 10µF  [1210_280]  (hidden comment: 885012209073)
C76  VDC_V: 50V  ValueDisplayed: 10µF  [1210_280]  (hidden comment: 885012209073)
C77  VDC_V: 50V  ValueDisplayed: 10µF  [1210_280]  (hidden comment: 885012209073)
C78  VDC_V: 50V  ValueDisplayed: 10µF  [1210_280]  (hidden comment: 885012209073)
C79  VDC_V: 35V  ValueDisplayed: 150uF  [SM_RADIAL_10BMM]  (hidden comment: UCL1V151MCL6GS)
C80  Cap_F: 100nF  [0603]  (hidden comment: 885012206095)
C81  Cap_F: 100nF  [0603]  (hidden comment: 885012206095)
C82  Cap_F: 100nF  [0603]  (hidden comment: 885012206095)
C83  Cap_F: 100nF  [0603]  (hidden comment: 885012206095)
C84  Cap_F: 4.7µF  VDC_V: 25V  [0805_HV]  (hidden comment: 885012107018)
C85  Cap_F: 1µF  VDC_V: 50V  [0805_HV]  (hidden comment: 885012207103)
C86  Cap_F: 100nF  [0603]  (hidden comment: 885012206095)
C87  VDC_V: 25V  ValueDisplayed: 4.7uF  [0603]  (hidden comment: GRM188C81E475KE11D)
C88  VDC_V: 35V  ValueDisplayed: 150uF  [SM_RADIAL_10BMM]  (hidden comment: UCL1V151MCL6GS)
C89  VDC_V: 35V  ValueDisplayed: 150uF  [SM_RADIAL_10BMM]  (hidden comment: UCL1V151MCL6GS)
C90  VDC_V: 35V  ValueDisplayed: 150uF  [SM_RADIAL_10BMM]  (hidden comment: UCL1V151MCL6GS)
C201  Cap_F: 100nF  [0603]  (hidden comment: 885012206095)
D22  value 15V  [SOD-323]  (hidden comment: CMDZ15L)
D23  BAT46WJ,115  [SOD-323F]
D24  BAT46WJ,115  [SOD-323F]
D25  value 15V  [SOD-323]  (hidden comment: CMDZ15L)
D26  value Green  [WL_SMCW_GREEN_1206]  (hidden comment: 150120VS75000)
D27  value Green  [WL_SMCW_GREEN_1206]  (hidden comment: 150120VS75000)
D28  value Green  [WL_SMCW_GREEN_1206]  (hidden comment: 150120VS75000)
D29  value 5.1V  [SOD-123]  (hidden comment: MMSZ4689T3G)
D30  BAS40-04-7-F  [SOT-23L]
J2  999-11-113-10-000000  [Mill-Max_999-11-113-10-000000]  (value not drawn)
J3  691236510003  [Wurth_691236510003]  (value not drawn)
J4  999-11-113-10-000000  [Mill-Max_999-11-113-10-000000]  (value not drawn)
J5  61900419521  [FP-22-05-3041_HDR4-MFG]  (value not drawn)
J6  999-11-113-10-000000  [Mill-Max_999-11-113-10-000000]  (value not drawn)
J7  691236510003  [Wurth_691236510003]  (value not drawn)
J11  999-11-113-10-000000  [Mill-Max_999-11-113-10-000000]  (value not drawn)
L8  ValueDisplayed: 5.5uH  [WE-HC6]  (hidden comment: 744325550)
NT1  Net-Tie  [Net-Tie_10milWide_30milLong]  (net tie, no BOM)
Q15  CSD18531Q5A  [DQJ0008A]
Q16  CSD18531Q5A  [DQJ0008A]
Q17  CSD18531Q5A  [DQJ0008A]
Q18  CSD18531Q5A  [DQJ0008A]
Q19  NTTFS5C670NLTAG  [Power_WDFN-8]
Q20  NTTFS5C670NLTAG  [Power_WDFN-8]
Q21  NTTFS5C670NLTAG  [Power_WDFN-8]
Q22  NTTFS5C670NLTAG  [Power_WDFN-8]
Q23  value SUM110P06  [DDPAK]  (hidden comment: SUM110P06-07L-E3)
R87  ValueDisplayed: 0.002  [2512]  (hidden comment: 580070763001)
R88  Res_ohm: 10  [FP-560050316012_0603-IPC_B]  (hidden comment: 560050316012)
R89  Res_ohm: 10  [FP-560050316012_0603-IPC_B]  (hidden comment: 560050316012)
R90  DNP  [0603]
R91  ValueDisplayed: 0  [0603]  (hidden comment: RMCF0603ZT0R00)
R92  ValueDisplayed: 0  [0603]  (hidden comment: RMCF0603ZT0R00)
R93  Res_ohm: 10  [FP-560050316012_0603-IPC_B]  (hidden comment: 560050316012)
R94  ValueDisplayed: 0  [0603]  (hidden comment: RMCF0603ZT0R00)
R95  ValueDisplayed: 0  [0603]  (hidden comment: RMCF0603ZT0R00)
R96  ValueDisplayed: 0.005  [2512]  (hidden comment: 580070763005)
R97  Res_ohm: 10  [FP-560050316012_0603-IPC_B]  (hidden comment: 560050316012)
R98  ValueDisplayed: 0  [0603]  (hidden comment: RMCF0603ZT0R00)
R99  ValueDisplayed: 113k  [0603]  (hidden comment: RC0603FR-07113KL)
R100  ValueDisplayed: 2.58k  [0603]  (hidden comment: RT0603DRE072K58L)
R101  ValueDisplayed: 249k  [0603]  (hidden comment: RC0603FR-07249KL)
R102  ValueDisplayed: 15.0k  [0603]  (hidden comment: RC0603FR-0715KL)
R103  ValueDisplayed: 4.22k  [0603]  (hidden comment: RT0603DRE074K22L)
R104  ValueDisplayed: 1.00k  [0603]  (hidden comment: RC0603FR-071KL)
R105  ValueDisplayed: 1.00k  [0603]  (hidden comment: RC0603FR-071KL)
R106  ValueDisplayed: 1.00k  [0603]  (hidden comment: RC0603FR-071KL)
R107  ValueDisplayed: 66.5k  [0603]  (hidden comment: RC0603FR-0766K5L)
R108  ValueDisplayed: 24.3k  [0603]  (hidden comment: CRCW060324K3FKEA)
R109  ValueDisplayed: 3.30k  [0603]  (hidden comment: RC0603FR-073K3L)
R110  ValueDisplayed: 1.00k  [2010]  (hidden comment: CRCW20101K00FKEF)
R111  ValueDisplayed: 30.1k  [0603]  (hidden comment: RT0603BRD0730K1L)
R112  ValueDisplayed: 5.23k  [0603]  (hidden comment: RT0603BRD075K23L)
R113  ValueDisplayed: 100k  [0603]  (hidden comment: CRCW0603100KDHEAP)
R201  ValueDisplayed: 1.80k  [0603]  (hidden comment: RC0603FR-071K8L)
U10  BQ25751RRVT  [RRV0036A-MFG]

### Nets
3V3: D26.2(A) D27.2(A) D28.2(A)
AGND: C69.2 C70.1 C82.1 C83.2 C85.2 C86.1 C201.1 NT1.2 R103.1 R107.1 R108.1 R109.1 R111.1
SGND: C64.2 C65.2 C66.2 C67.2 C68.2 C71.2 C72.2 C73.2 C74.2 C75.2 C76.2 C77.2 C78.2 C79.2(-) C84.2 C87.2 C88.2(-) C89.2(-) C90.2(-) D29.2(A) D30.1(A) J3.1 J5.1 J7.3 NT1.1 Q21.1(S) Q21.2(S) Q21.3(S) Q22.1(S) Q22.2(S) Q22.3(S) R113.1 U10.17(MODE) U10.22(PGND) U10.37(PGND)
+24V: C64.1 C65.1 C66.1 C67.1 C85.1 C86.2 J6.1 J11.1 Q15.5(D) Q15.6(D) Q15.7(D) Q15.8(D) Q15.9(D) R99.2 U10.33(VAC) ; off-sheet +24V
BAT: C88.1(+) C89.1(+) C90.1(+) D25.1(K) J6.2 Q23.3(S) R96.1 R97.1 R101.1 ; off-sheet BAT
BAT_DRV: Q17.4(G) Q18.4(G) U10.15(BAT_DRV) ; off-sheet BAT_DRV
BAT_SRC: Q17.1(S) Q17.2(S) Q17.3(S) Q18.1(S) Q18.2(S) Q18.3(S) U10.16(BAT_SRC) ; off-sheet BAT_SRC
BQ_CE: U10.7(~{CE}) ; off-sheet BQ_CE
BQ_INT: U10.3(~{INT}) ; off-sheet BQ_INT
DRV_SUP: C84.1 D23.2(A) D24.2(A) R98.2 U10.23(DRV_SUP) ; off-sheet DRV_SUP
REG_N: C87.1 R98.1 R112.2 U10.24(REGN) ; off-sheet REG_N
SCL: J5.2 U10.1(SCL) ; off-sheet SCL
SDA: J5.3 U10.2(SDA) ; off-sheet SDA
SYSTEM: C68.1 C71.1 C72.1 C73.1 C74.1 J2.1 Q18.5(D) Q18.6(D) Q18.7(D) Q18.8(D) Q18.9(D) Q20.5(D) Q20.6(D) Q20.7(D) Q20.8(D) Q20.9(D) R87.2 R89.2 U10.32(SYS) ; off-sheet SYSTEM
NetC69_1: C69.1 R88.1 U10.30(ACP)
NetC70_2: C70.2 R89.1 U10.29(ACN)
NetC75_1: C75.1 C76.1 C77.1 C78.1 C79.1(+) Q17.5(D) Q17.6(D) Q17.7(D) Q17.8(D) Q17.9(D) Q19.5(D) Q19.6(D) Q19.7(D) Q19.8(D) Q19.9(D) R93.1 R96.2
NetC80_1: C80.1 L8.1 Q20.1(S) Q20.2(S) Q20.3(S) Q21.5(D) Q21.6(D) Q21.7(D) Q21.8(D) Q21.9(D) U10.28(SW1)
NetC80_2: C80.2 D23.1(K) U10.26(BTST1)
NetC81_1: C81.1 L8.2 Q19.1(S) Q19.2(S) Q19.3(S) Q22.5(D) Q22.6(D) Q22.7(D) Q22.8(D) Q22.9(D) U10.18(SW2)
NetC81_2: C81.2 D24.1(K) U10.20(BTST2)
NetC82_2: C82.2 R93.2 U10.14(SRP)
NetC83_1: C83.1 R97.2 U10.13(SRN)
NetC201_2: C201.2 R201.1
NetD22_1: D22.1(K) Q15.4(G) Q16.4(G) U10.31(ACDRV)
NetD22_2: D22.2(A) Q15.1(S) Q15.2(S) Q15.3(S) Q16.1(S) Q16.2(S) Q16.3(S)
NetD25_2: D25.2(A) Q23.1(G) R113.2
NetD26_1: D26.1(K) R104.1
NetD27_1: D27.1(K) R105.1
NetD28_1: D28.1(K) R106.1
NetD29_1: D29.1(K) D30.2(K)
NetD30_3: D30.3(C) R110.1 R111.2 R112.1 U10.8(TS)
NetJ2_2: J2.2 J3.3 J4.2
NetJ4_1: J4.1 J7.1 Q23.2(D)
NetJ7_2: J7.2 R110.2
NetJ11_2: J11.2 Q16.5(D) Q16.6(D) Q16.7(D) Q16.8(D) Q16.9(D) R87.1 R88.2 R90.1
NetQ19_4: Q19.4(G) R92.1
NetQ20_4: Q20.4(G) R91.2
NetQ21_4: Q21.4(G) R94.1
NetQ22_4: Q22.4(G) R95.1
NetR90_2: R90.2 R99.1 R100.2 U10.34(ACUV)
NetR91_1: R91.1 U10.27(HIDRV1)
NetR92_2: R92.2 U10.19(HIDRV2)
NetR94_2: R94.2 U10.25(LODRV1)
NetR95_2: R95.2 U10.21(LODRV2)
NetR100_1: R100.1 R103.2 U10.35(ACOV)
NetR101_2: R101.2 R102.1 U10.12(FB)
NetR102_2: R102.2 U10.11(FBG)
NetR104_2: R104.2 U10.5(STAT2)
NetR105_2: R105.2 U10.4(STAT1)
NetR106_2: R106.2 U10.6(~{PG})
NetR107_2: R107.2 U10.36(FSW_SYNC)
NetR108_2: R108.2 R201.2 U10.9(ICHG)
NetR109_2: R109.2 U10.10(ILIM_HIZ)

Not connected (* = marked no-connect by the designer): J3 2; J5 4

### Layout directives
rule Clearance Constraint [Clearance = 10mil]: AGND, BAT, BAT_SRC, NetC75_1, NetD22_2, NetJ11_2
rule Clearance Constraint [Clearance = 9mil]: BAT_DRV, DRV_SUP, NetC69_1, NetC70_2, NetC80_1, NetC80_2, NetC81_1, NetC81_2, NetC82_2, NetC83_1, NetD22_1, NetD25_2, NetD29_1, NetJ4_1, NetJ7_2, NetQ19_4, NetQ20_4, NetQ21_4, NetQ22_4, NetR90_2, NetR91_1, NetR92_2, NetR94_2, NetR95_2, NetR100_1, NetR101_2, NetR102_2, NetR104_2, NetR105_2, NetR106_2, NetR107_2, NetR108_2, NetR109_2, REG_N, SYSTEM

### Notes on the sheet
- ISystem(max) = 12A - Ibatt
- (near J2) V1: short
- (near J2) V2: open
- (near J3) System +
- (near J3) GND
- (near J4) V1: open
- (near J4) V2: short
- BQ-Studio Connector
- (near J6) V1: open
- (near J6) V2: short
- Vbat(nom) = 27V
- (near J7) Batt+
- UVLO @ 20V
- OVP @ 30.1V
- (near U10) Fsw = 400 kHz
- Icharge(limit) = 2.06 A
- (near J7) Batt-
- (near J7) TS
- Battery
- Assembly Notes:
- "DNP" = "do not populate"
- Ref. Desg. > 199 should be added on the board
- (near R111) Iac(limit) = 15 A
- Variant V1: using BQ25751
- Variant V2: stand alone (DNP BQ25751 the whole section)
- In case power path is not used, do not populate Q15, Q16, Q17, Q18, D22 and populate J11
- PMP31276RevB is built on PMP31276RevA

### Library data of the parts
C64-C68 C71-C78 = CMP-0081135-1: CAP, CERM, 10 µF, 50 V,+/- 10%, X7R, 1210; Manufacturer: Wuerth; TaMin_C: -55°C; ESR_ohm: 1m; Polarized: N; SizeAreaWB_mm2: 14.7; Value1: 0.001 ohm; U/M: EA; Value: 10uF; TaMax_C: 125°C; SizeZ_mm: 2.8; SizeX_mm: 3.2; SizeY_mm: 2.5; Cap_Case: 1210; SizeArea_mm2: 8; AEC Category: Q200
C69 C70 = CMP-0007424-4: CAP, CERM, 0.47 uF, 25 V, +/- 10%, X7R, 0603; Manufacturer: MuRata; TaMin_C: -55°C; Polarized: N; SizeAreaWB_mm2: 4.68; Value1: Unknown; U/M: EA; Value: 0.47uF; TaMax_C: 125°C; SizeZ_mm: 1; SizeX_mm: 1.6; SizeY_mm: 0.8; Value2: 25V; SizeArea_mm2: 1.28; AEC Category: Q200
C79 C88-C90 = CMP-0011092-1: CAP, AL, 150 uF, 35 V, +/- 20%, 0.1 ohm, SMD; Manufacturer: Nichicon; TaMin_C: -55°C; ESR_ohm: 100m; Polarized: Y; SizeAreaWB_mm2: 159.9; Value1: 0.1 ohm; U/M: EA; Value: 150uF; TaMax_C: 105°C; SizeZ_mm: 10.2; SizeX_mm: 11; SizeY_mm: 10.3; Cap_Case: 10x10; SizeArea_mm2: 113.3; CompType: Capacitor; Cap_F: 150µF; IRMS_A: 850mA; AEC Category: Q200
C80-C83 C86 C201 = CMP-0006837-3: as C50 on sheet PMP31276 Rev_B LLC Schematic
C84 = CMP-0007696-2: CAP, CERM, 4.7 uF, 25 V, +/- 10%, X5R, 0805; Manufacturer: Wurth Elektronik; TaMin_C: -55°C; Polarized: N; SizeAreaWB_mm2: 6.75; Value1: Unknown; U/M: EA; Value: 4.7uF; TaMax_C: 125°C; SizeZ_mm: 1.45; SizeX_mm: 2; SizeY_mm: 1.25; Cap_Case: 0805; SizeArea_mm2: 2.5; AEC Category: Q200
C85 = CMP-0007696-2: CAP, CERM, 1 uF, 50 V, +/- 10%, X7R, 0805; Manufacturer: Wurth Elektronik; TaMin_C: -55°C; Polarized: N; SizeAreaWB_mm2: 6.75; Value1: Unknown; U/M: EA; Value: 1uF; TaMax_C: 125°C; SizeZ_mm: 1.45; SizeX_mm: 2; SizeY_mm: 1.25; Cap_Case: 0805; SizeArea_mm2: 2.5; AEC Category: Q200
C87 = CMP-0007297-4: CAP, CERM, 4.7 uF, 25 V, +/- 10%, X6S, 0603; Manufacturer: MuRata; TaMin_C: -55°C; Polarized: N; SizeAreaWB_mm2: 4.68; Value1: Unknown; U/M: EA; Value: 4.7uF; TaMax_C: 105°C; SizeZ_mm: 1; SizeX_mm: 1.6; SizeY_mm: 0.8; SizeArea_mm2: 1.28; Cap_F: 4.7µF; AEC Category: Q200
D22 D25 = CMP-0005833-4: Diode, Zener, 15 V, 200 mW, SOD-323; Manufacturer: Central semiconductor; SizeY_mm: 1.35; RJA_CperW: 350; SizeX_mm: 2.7; AEC Category: Q101; SizeAreaWB_mm2: 8.695; SizeZ_mm: 1; Power_W: 200mW; SizeArea_mm2: 3.645; Value1: 0.2W
D23 D24 = CMP-0076946-2: Diode, Schottky, 100 V, 0.25 A, SOD-323F; Manufacturer: Nexperia; SizeAreaWB_mm2: 7.875; Value2: 0.85V; SizeX_mm: 2.5; Green_REACh: Incomplete; SizeArea_mm2: 3.125; Vf_V: 850mV; Green_Lifecycle: Not Set; Vr_V: 100V; TJmax_C: 150°C; Value1: 0.25A; Io_A: 250mA; SizeZ_mm: 0.8; Value: 100V; AEC Category: Q101; SizeY_mm: 1.25
D26-D28 = CMP-0002936-3: LED, Green, SMD; Manufacturer: Wurth Elektronik; Vr_V: 5V; Power_TotalModule: 72mW; Value2: 2V; Value1: 0.072W; Angle: 140; Type: AlInGaP; Io_A: 20mA; Ir_A: 10µA; Tjmax_C: 85°C
D29 = CMP-0005786-2: Diode, Zener, 5.1 V, 500 mW, SOD-123; Manufacturer: ON Semiconductor; SizeZ_mm: 1.35; AEC Category: Q101; Power_W: 500mW; SizeArea_mm2: 6.545; SizeX_mm: 3.85; RJA_CperW: 340; SizeY_mm: 1.7; Value1: 0.5W; SizeAreaWB_mm2: 13.095
D30 = CMP-0076970-1: Diode, Schottky, 40 V, 0.2 A, SOT-23; Manufacturer: Diodes Inc.; SizeAreaWB_mm2: 14.0; Vr_V: 40V; SizeArea_mm2: 7.5; TJmax_C: 125°C; AEC Category: Q101; Value: 40V; SizeZ_mm: 1.1; Green_REACh: Incomplete; Io_A: 200mA; Vf_V: 1V; SizeY_mm: 3.0; Green_Lifecycle: Not Set; U/M: EA; Value1: 0.2A; SizeX_mm: 2.5
J2 J4 J6 J11 = CMP-0055045-1: Shorting Jumper, 7.62mm, 2 Position, Gold, TH; Manufacturer: Mill-Max; CNHeader: FALSE; Gender: Male; Pitch_mm: 7.62; Cert_UL: Y
J3 J7 = CMP-0079043-1: Terminal Block, 5.08mm, 3x1, R/A, TH; Manufacturer: Wurth Elektronik; Pitch_mm: 5.08; Cert_VDE: Y; Gender: Female; Voltage_V: 300V; Current_A: 20A; Row_Count: 1
J5 = CMP-0089047-1: Manufacturer: Wuerth; Current_A: 4A; Row_Count: 1; Voltage_V: 500V; ContactFinish: Tin,Nickel
L8 = CMP-0063967-1: Inductor, Shielded Drum Core, Superflux, 5.5 uH, 10 A, 0.0112 ohm, SMD; Manufacturer: Wurth Elektronik; Isat: 12A @ 30% inductance drop; Irms: 10A @ 50C rise; Green_Lifecycle: Active; SizeAreaWB_mm2: 158.6; DCR_ohm: 11.2m; Green_REACh: Passed; Value: 5.5uH; Imax_A: 10A; SizeZ_mm: 5; SizeX_mm: 11; SizeY_mm: 10.2; SizeArea_mm2: 112.2; Ind_H: 5.5µH; AEC Category: Q200
NT1 = CMP-0078142-5: Single point connection between nets.
Q15-Q18 = CMP-0000810-1: MOSFET, N-CH, 60 V, 100 A, DQJ0008A (VSONP-8); Alternate Manufacturer: None; Manufacturer: Texas Instruments; SizeZ_mm: 1.1; ChType: N; Value2: 36 nC; Value1: 0.005; VdsMax_V: 60V; SizeX_mm: 6; SizeY_mm: 4.9; Vgs_V: 20V; Value: 60V; Rdson45_ohm: 5.8m; SizeArea_mm2: 29.4; AEC Category: Q101; IdsMax_A: 100A; SizeAreaWB_mm2: 55.2; U/M: EA; QgTyp_nC: 36
Q19-Q22 = CMP-0000855-1: MOSFET, N-CH, 60 V, 70 A, 8-PowerWDFN; Alternate Manufacturer: None; Manufacturer: ON Semiconductor; SizeZ_mm: 0.8; ChType: N; Value2: 9 nC; Value1: 0.013; VdsMax_V: 60V; SizeX_mm: 3.3; Vgs_V: 20V; Rdson45_ohm: 13.3m; SizeArea_mm2: 10.89; AEC Category: Q101; IdsMax_A: 70A; SizeAreaWB_mm2: 18.49; U/M: EA; QgTyp_nC: 9.5
Q23 = CMP-0000151-4: MOSFET, P-CH, -60 V, -110 A, DDPAK; Manufacturer: Vishay-Siliconix; Alternate Manufacturer: None; Rdson45_ohm: 8.8m; ChMode: Enhancement; IdsMax_A: -110A; Value2: 230 nC; Vgs_V: -20V; ChType: P; QgTyp_nC: 230; SizeArea_mm2: 154.8892; VdsMax_V: -60V; SizeAreaWB_mm2: 209.6992; Value1: 0.008; AEC Category: Q101; SizeZ_mm: 4.445; SizeX_mm: 15.245; SizeY_mm: 10.16
R87 = CMP-0015819-2: RES, 0.002, 1%, 2 W, 2512; Manufacturer: Wuerth; Power_W: 2W; TempCo: ppm/C; Value_Code: 2L000; U/M: EA; Value: 0.002; Res_ohm: 2m; SizeX_mm: 6.3; SizeY_mm: 3.2; SizeZ_mm: 0.71; SizeArea_mm2: 20.16; AEC Category: Q200
R88 R89 R93 R97 = CMP-0087986-1: WRIS-KSKE Thick Film Resistors; Manufacturer: Wurth Electronics; Tolerance_%: 1%; AEC Qualified: No; TempCo: 100ppm/°C; Symbol Name: SYM-560050316012; Power_W: 250mW; SizeZ_mm: 0.55mm; VDC_V: 1.5811V; Value: 10
R90 = CMP-0021990-4: as R72 on sheet PMP31276 Rev_B LLC Schematic
R91 R92 R94 R95 R98 = CMP-0023343-3: as R61 on sheet PMP31276 Rev_B LLC Schematic
R96 = CMP-0015814-2: RES, 0.005, 1%, 2 W, 2512; Manufacturer: Wuerth; Power_W: 2W; TempCo: 100 ppm/C; Value_Code: 5L000; U/M: EA; Value: 0.005; EIA_Code: E96; Res_ohm: 5m; SizeX_mm: 6.3; SizeY_mm: 3.2; SizeZ_mm: 0.71; SizeArea_mm2: 20.16; AEC Category: Q200
R99 = CMP-0022754-4: RES, 113 k, 1%, 0.1 W, 0603; Manufacturer: Yageo; Power_W: 100mW; TempCo: 100 ppm/C; Value: 113k; EIA_Code: E96; SizeX_mm: 1.6; SizeY_mm: 0.8; SizeZ_mm: 1; Value2: 0.1W; SizeArea_mm2: 1.28; AEC Qualified: N; VDC_V: 75V; AEC Category: Q200; SizeAreaWB_mm2: 4.68
R100 = CMP-0025067-3: RES, 2.58 k, 0.5%, 0.1 W, 0603; Manufacturer: Yageo America; Power_W: 100mW; TempCo: 50 ppm/C; Value_Code: 2k58; U/M: EA; Value: 2.58k; EIA_Code: E192; SizeX_mm: 1.6; SizeY_mm: 0.8; SizeZ_mm: 1; Value2: 0.1W; SizeArea_mm2: 1.28; VDC_V: 75V; AEC Category: Q200
R101 = CMP-0022941-4: RES, 249 k, 1%, 0.1 W, 0603; Manufacturer: Yageo; Power_W: 100mW; TempCo: 100 ppm/C; Value: 249k; EIA_Code: E96; SizeX_mm: 1.6; SizeY_mm: 0.8; SizeZ_mm: 1; Value2: 0.1W; SizeArea_mm2: 1.28; AEC Qualified: N; VDC_V: 75V; AEC Category: Q200; SizeAreaWB_mm2: 4.68
R102 = CMP-0022816-5: as R85 on sheet PMP31276 Rev_B LLC Schematic
R103 = CMP-0025339-3: RES, 4.22 k, 0.5%, 0.1 W, 0603; Manufacturer: Yageo America; Power_W: 100mW; TempCo: 50 ppm/C; Value_Code: 4k22; U/M: EA; Value: 4.22k; EIA_Code: E192; SizeX_mm: 1.6; SizeY_mm: 0.8; SizeZ_mm: 1; Value2: 0.1W; SizeArea_mm2: 1.28; VDC_V: 75V; AEC Category: Q200
R104-R106 = CMP-0022895-5: as R84 on sheet PMP31276 Rev_B LLC Schematic
R107 = CMP-0023232-5: RES, 66.5 k, 1%, 0.1 W, 0603; Manufacturer: Yageo; Power_W: 100mW; TempCo: 100 ppm/C; Value_Code: 66k5; Value: 66.5k; EIA_Code: E96; SizeZ_mm: 1; Value2: 0.1W; SizeArea_mm2: 1.28; AEC Qualified: N; VDC_V: 75V; AEC Category: Q200; SizeAreaWB_mm2: 4.68; SizeX_mm: 1.6; SizeY_mm: 0.8
R108 = CMP-0022236-4: RES, 24.3 k, 1%, 0.1 W, AEC-Q200 Grade 0, 0603; Manufacturer: Vishay-Dale; Power_W: 100mW; TempCo: 100 ppm/C; Value_Code: 24k3; Value: 24.3k; EIA_Code: E96; SizeX_mm: 1.6; SizeY_mm: 0.8; SizeZ_mm: 1; Value2: 0.1W; SizeArea_mm2: 1.28; AEC Qualified: Y; VDC_V: 75V; AEC Category: Q200; AEC Grade: 0
R109 = CMP-0023081-5: RES, 3.30 k, 1%, 0.1 W, 0603; Manufacturer: Yageo; Power_W: 100mW; TempCo: 100 ppm/C; Value_Code: 3k30; Value: 3.30k; Res_ohm: 3.3k; SizeX_mm: 1.6; SizeY_mm: 0.8; SizeZ_mm: 1; Value2: 0.1W; SizeArea_mm2: 1.28; AEC Qualified: N; VDC_V: 75V; AEC Category: Q200; SizeAreaWB_mm2: 4.68
R110 = CMP-0016277-2: RES, 1.00 k, 1%, 0.75 W, AEC-Q200 Grade 0, 2010; Manufacturer: Vishay-Dale; Power_W: 750mW; TempCo: 100 ppm/C; Value_Code: 1k00; U/M: EA; Value: 1.00k; EIA_Code: E96; Res_ohm: 1k; SizeX_mm: 5; SizeY_mm: 2.5; SizeZ_mm: 1.66; Value2: 0.75W; SizeArea_mm2: 12.5; AEC Qualified: Y; VDC_V: 400V; AEC Grade: 0; AEC Category: Q200
R111 = CMP-0024096-3: RES, 30.1 k, 0.1%, 0.1 W, 0603; Manufacturer: Yageo America; Power_W: 100mW; TempCo: 25 ppm/C; Value_Code: 30k1; U/M: EA; Value: 30.1k; EIA_Code: E192; SizeX_mm: 1.6; SizeY_mm: 0.8; SizeZ_mm: 1; Value2: 0.1W; SizeArea_mm2: 1.28; VDC_V: 75V; AEC Category: Q200
R112 = CMP-0024368-2: RES, 5.23 k, 0.1%, 0.1 W, 0603; Manufacturer: Yageo America; Power_W: 100mW; TempCo: 25 ppm/C; Value_Code: 5k23; U/M: EA; Value: 5.23k; EIA_Code: E192; SizeX_mm: 1.6; SizeY_mm: 0.8; SizeZ_mm: 1; Value2: 0.1W; SizeArea_mm2: 1.28; VDC_V: 75V; AEC Category: Q200
R113 = CMP-0086261-1: RES, 100 k, 0.5%, 0.1 W, AEC-Q200 Grade 0, 0603; Manufacturer: Vishay-Dale; EIA_Code: E192; SizeZ_mm: 1; Power_W: 100mW; Value2: 0.1W; Value: 100k; SizeAreaWB_mm2: 4.68; AEC Qualified: Y; TempCo: 50 ppm/C; SizeArea_mm2: 1.28; AEC Category: Q200; SizeX_mm: 1.6; SizeY_mm: 0.8; AEC Grade: 0
R201 = CMP-0022892-5: RES, 1.80 k, 1%, 0.1 W, 0603; Manufacturer: Yageo; Power_W: 100mW; TempCo: 100 ppm/C; Value_Code: 1k80; Value: 1.80k; Res_ohm: 1.8k; SizeX_mm: 1.6; SizeY_mm: 0.8; SizeZ_mm: 1; Value2: 0.1W; SizeArea_mm2: 1.28; AEC Qualified: N; VDC_V: 75V; AEC Category: Q200; SizeAreaWB_mm2: 4.68
U10 = CMP-0093459-1: Manufacturer: Texas Instruments; SizeZ_mm: 1mm; Standoff Height: 0mm; AEC Qualified: No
